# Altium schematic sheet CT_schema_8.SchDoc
size 226 x 144 mm
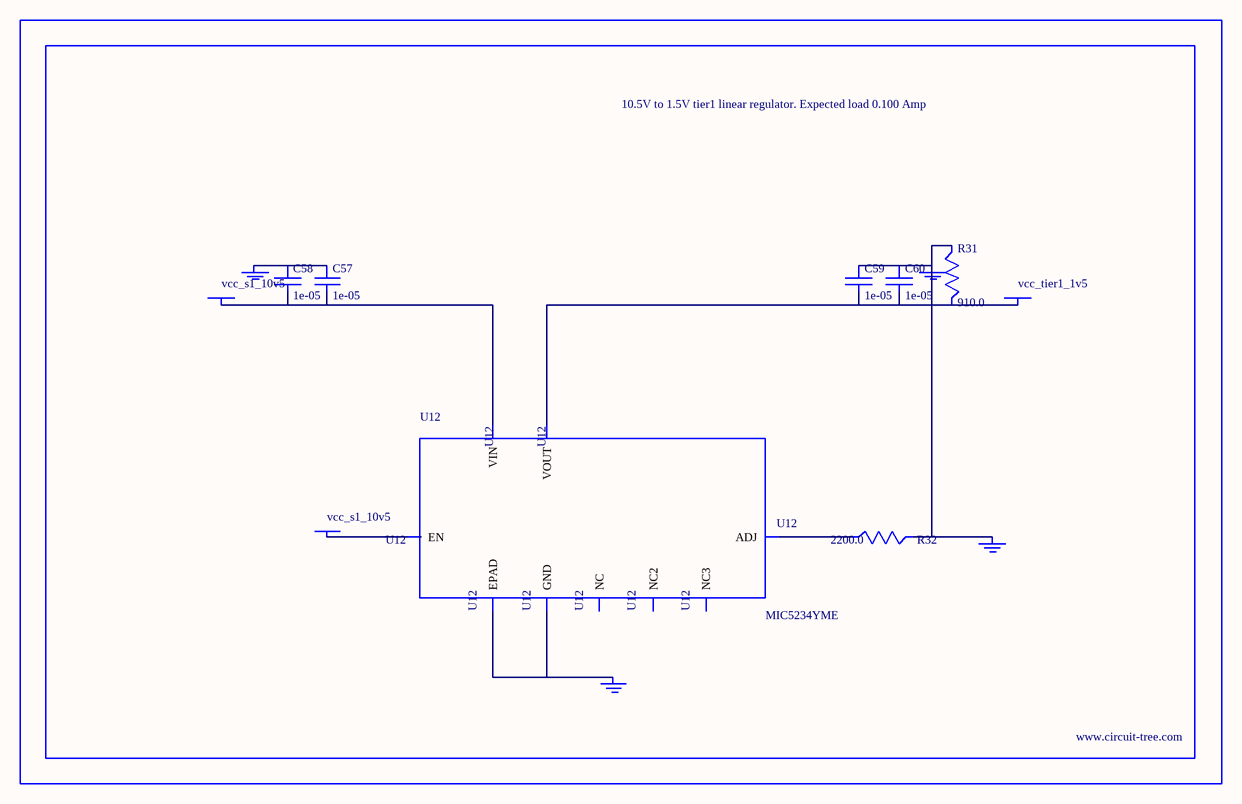
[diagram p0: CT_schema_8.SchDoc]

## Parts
BORDER7  (no value)
C57  1e-05  [C1210]
C58  1e-05  [C1210]
C59  1e-05  [C1210]
C60  1e-05  [C1210]
GND_INSTANCE_7_0  (no value)
GND_INSTANCE_7_1  (no value)
GND_INSTANCE_7_2  (no value)
GND_INSTANCE_7_3  (no value)
POWER_INSTANCE_7_0  vcc_tier1_1v5
POWER_INSTANCE_7_1  vcc_s1_10v5
POWER_INSTANCE_7_2  vcc_s1_10v5
R31  910.0  [R0603]
R32  2200.0  [R0603]
U12  MIC5234YME  [SOIC-8_EP]

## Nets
NetC57_1: C57.1 C58.1 GND_INSTANCE_7_3.0(GND)
NetC57_2: C57.2 C58.2 POWER_INSTANCE_7_2.0(PWR) U12.8(VIN)
NetC59_1: C59.1 C60.1 GND_INSTANCE_7_0.0(GND) GND_INSTANCE_7_1.0(GND) R31.1 R32.2
NetC59_2: C59.2 C60.2 POWER_INSTANCE_7_0.0(PWR) R31.2 U12.1(VOUT)
NetGND_INSTANCE_7_2_0: GND_INSTANCE_7_2.0(GND) U12.7(GND) U12.EPAD
NetPOWER_INSTANCE_7_1_0: POWER_INSTANCE_7_1.0(PWR) U12.5(EN)
NetR32_1: R32.1 U12.4(ADJ)

Not connected (* = marked no-connect by the designer): U12 2(NC) 3(NC2) 6(NC3)

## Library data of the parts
BORDER7 = BORDER_PAGE7
C57-C60 = C1210C106K5PACTU
GND_INSTANCE_7_0-GND_INSTANCE_7_3 = GND
POWER_INSTANCE_7_0-POWER_INSTANCE_7_2 = PWR
R31 = RC0603JR-07910RL
R32 = RC0603JR-072K2L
